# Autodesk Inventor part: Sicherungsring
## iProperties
Title: Sicherungsring
Created: 2005-06
Part Number: 368492
Material: Standard
Description: Sicherungsring
Vendor: Autodesk Inc.
Document SubType Name: Modeling
Standard: DIN 471
Designer: I.Baliuc
Size Designation: 30 x 1.5
Density: 1 g/cm^3
Abmessung: 30 x 1.5
Author: T.Messerschmitt
Revision Number: 368492
Comments: DIN 471 - 30 x 1.5
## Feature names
1. Körper [Extrusion]
